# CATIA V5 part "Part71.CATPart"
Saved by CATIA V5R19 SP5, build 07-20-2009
Part number: Part71
Bounding box of the stored display mesh (mm): x -84.817 to 129.555, y -55.6 to 35.826, z -10 to 27.57
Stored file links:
  C:\users\Shape\llll\catia\Navody na cvicenia\Part71.CATPart
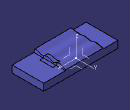
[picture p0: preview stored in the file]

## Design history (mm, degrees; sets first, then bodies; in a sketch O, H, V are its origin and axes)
AxisSystem1: origin (0, 0, 0), X (1, 0, 0), Y (0, 1, 0), Z (0, 0, 1)
Body1 (main body)
Body2 "doska"
  Body3 "model"
    Solid1: solid without history
  Assemble1: tool Body3
  Body4 "vyrezanie"
    Sketch1 on face of Solid1, origin (0, 0, 0), H (1, 0, 0), V (0, -1, 0)
      line L1 (76.8016, 27.7864) -> (55.1663, 27.7864)
      line L2 (55.1663, 27.7864) -> (55.1663, -9.5023)
      line L3 (55.1663, -9.5023) -> (76.8016, -9.5023)
      line L4 (76.8016, -9.5023) -> (76.8016, 27.7864)
      horizontal: L1 H, L3 H
      vertical: L2 V, L4 V
    Pad1: profile Sketch1, direction (0, 0, 1), length 41
  Remove1: tool Body4
Body5 "vlozka"
  Sketch2 on face of Solid3, origin (0, 0, 0), H (1, 0, 0), V (0, -1, 0)
    line L1 (43.0663, 35.5906) -> (88.5691, 35.5906)
    line L2 (88.5691, 35.5906) -> (88.5691, -17.855)
    line L3 (88.5691, -17.855) -> (43.0663, -17.855)
    line L4 (43.0663, -17.855) -> (43.0663, 35.5906)
    circle A1 centre (48.4196, 30.246) radius 2.7134
    circle A2 centre (83.1224, 30.246) radius 2.2228
    circle A3 centre (83.1224, -13.8298) radius 1.7921
    circle A4 centre (48.4196, -13.8298) radius 2.284
    horizontal: L1 H, L3 H
    vertical: L2 V, L4 V
  Pad2: profile Sketch2, direction (0, 0, -1), length 10
  Body6 "vyrezanie"
    Solid2: linked copy from another document
    Body7 "model"
      Solid3: linked copy from another document
      Thickness1: Thickness 25, Face face of Solid3
    Intersect1: tool Body7
  Assemble2: tool Body6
